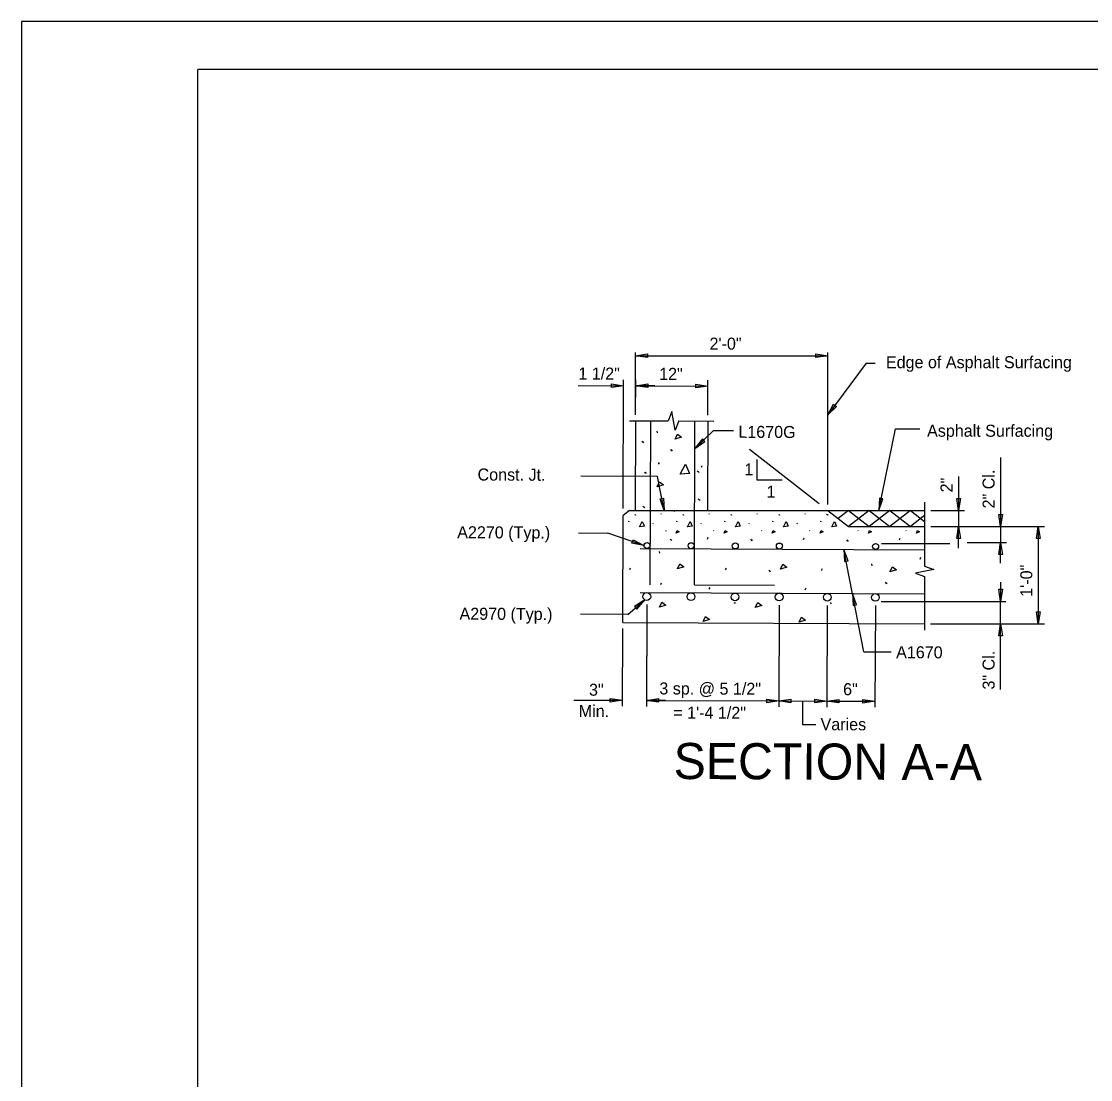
# Model space of a CAD drawing. Extents: x 2799.7 to 2896, y 515.2 to 573.9.
# Drawn here: x 2799.69 to 2829.32, y 544.56 to 573.89 of the extents above; entities that cross this region are included whole.
import ezdxf

# ---------------------------------------------------------------- set-up
doc = ezdxf.new("R2010")
doc.units = 0
for name, color, linetype in [('BR_AUTO DIMENSION', 7, 'Continuous'), ('BR_BORDER LINES', 7, 'Continuous'), ('BR_CONCRETE', 7, 'Continuous'), ('BR_DETAILS', 7, 'Continuous'), ('BR_REBAR', 7, 'Continuous'), ('BR_TABLE LINES', 7, 'Continuous'), ('BR_TEXT', 7, 'Continuous'), ('Level 31', 7, 'Continuous')]:
    doc.layers.add(name, color=color, linetype=linetype)

msp = doc.modelspace()

# ---------------------------------------------------------------- linework, layer by layer
at = {"layer": 'BR_AUTO DIMENSION'}
for p, q in [((2816.709, 562.987), (2816.709, 564.707)), ((2822.042, 560.501), (2822.042, 564.707)), ((2816.709, 564.623), (2822.042, 564.623)), ((2823.098, 564.417), (2822.042, 562.98)), ((2823.098, 564.417), (2823.349, 564.417)), ((2815.124, 563.797), (2816.38, 563.792)), ((2816.366, 560.383), (2816.38, 563.958)), ((2816.71, 562.987), (2816.714, 563.957)), ((2816.71, 562.987), (2816.714, 563.957)), ((2817.246, 563.788), (2816.713, 563.79)), ((2816.713, 563.79), (2818.713, 563.782)), ((2818.71, 562.979), (2818.714, 563.949)), ((2818.872, 562.548), (2818.354, 562.053)), ((2818.872, 562.548), (2819.425, 562.546)), ((2823.449, 560.334), (2823.908, 562.594)), ((2823.908, 562.594), (2824.59, 562.594)), ((2819.864, 562.029), (2821.798, 560.525)), ((2820.074, 561.744), (2820.074, 561.182)), ((2826.826, 561.801), (2826.826, 559.89)), ((2817.315, 561.277), (2815.196, 561.286)), ((2817.502, 560.334), (2817.315, 561.277)), ((2820.074, 561.182), (2820.772, 561.182)), ((2825.659, 561.271), (2825.659, 560.334)), ((2824.887, 560.334), (2825.826, 560.334)), ((2825.659, 560.334), (2825.659, 559.89)), ((2815.126, 559.709), (2815.941, 559.706)), ((2816.937, 559.364), (2815.941, 559.706)), ((2824.887, 559.89), (2825.826, 559.89)), ((2824.887, 559.89), (2828.037, 559.89)), ((2824.887, 559.89), (2826.992, 559.89)), ((2825.659, 559.288), (2825.659, 559.89)), ((2826.826, 559.89), (2826.826, 559.445)), ((2827.87, 559.89), (2827.87, 557.19)), ((2823.525, 559.418), (2825.421, 559.418)), ((2825.895, 559.445), (2826.992, 559.445)), ((2826.062, 559.445), (2826.992, 559.445)), ((2826.826, 558.869), (2826.826, 559.445)), ((2826.826, 558.912), (2826.826, 559.445)), ((2823.036, 556.418), (2822.484, 559.253)), ((2826.826, 558.348), (2826.826, 557.814)), ((2816.499, 557.45), (2816.968, 557.854)), ((2817.022, 557.722), (2817.01, 554.902)), ((2817.021, 557.674), (2817.01, 554.902)), ((2820.688, 557.707), (2820.677, 554.887)), ((2820.688, 557.707), (2820.677, 554.887)), ((2822.021, 557.701), (2822.01, 554.882)), ((2822.021, 557.701), (2822.01, 554.882)), ((2823.355, 557.696), (2823.343, 554.876)), ((2823.519, 557.814), (2826.968, 557.814)), ((2826.826, 557.19), (2826.826, 557.814)), ((2816.499, 557.45), (2815.188, 557.456)), ((2816.352, 557.058), (2816.343, 554.905)), ((2824.886, 557.19), (2828.037, 557.19)), ((2826.826, 555.369), (2826.826, 557.19)), ((2826.826, 556.656), (2826.826, 557.19)), ((2823.036, 556.418), (2823.788, 556.415)), ((2815.002, 555.077), (2816.344, 555.072)), ((2817.011, 555.069), (2820.677, 555.054)), ((2817.544, 555.067), (2817.011, 555.069)), ((2820.677, 555.054), (2822.011, 555.048)), ((2821.34, 555.051), (2821.34, 554.396)), ((2822.011, 555.048), (2823.344, 555.043)), ((2821.34, 554.396), (2821.706, 554.396))]:
    msp.add_line(p, q, dxfattribs=at)
for points in [[(2817.042, 564.573), (2816.709, 564.623), (2817.042, 564.673)], [(2821.709, 564.673), (2822.042, 564.623), (2821.709, 564.573)], [(2816.047, 563.843), (2816.38, 563.792), (2816.046, 563.743)], [(2817.046, 563.739), (2816.713, 563.79), (2817.047, 563.839)], [(2817.046, 563.739), (2816.713, 563.79), (2817.047, 563.839)], [(2818.38, 563.833), (2818.713, 563.782), (2818.379, 563.733)], [(2822.28, 563.219), (2822.042, 562.98), (2822.199, 563.278)], [(2818.561, 562.32), (2818.354, 562.053), (2818.63, 562.247)], [(2817.486, 560.671), (2817.502, 560.334), (2817.388, 560.651)], [(2823.466, 560.671), (2823.449, 560.334), (2823.564, 560.651)], [(2825.709, 560.668), (2825.659, 560.334), (2825.609, 560.668)], [(2826.876, 560.223), (2826.826, 559.89), (2826.776, 560.223)], [(2825.609, 559.557), (2825.659, 559.89), (2825.709, 559.557)], [(2825.609, 559.557), (2825.659, 559.89), (2825.709, 559.557)], [(2827.82, 559.557), (2827.87, 559.89), (2827.92, 559.557)], [(2816.643, 559.518), (2816.942, 559.363), (2816.61, 559.423)], [(2826.776, 559.112), (2826.826, 559.445), (2826.876, 559.112)], [(2826.776, 559.112), (2826.826, 559.445), (2826.876, 559.112)], [(2822.597, 558.935), (2822.484, 559.253), (2822.499, 558.916)], [(2822.835, 557.714), (2822.722, 558.032), (2822.736, 557.695)], [(2826.876, 558.148), (2826.826, 557.814), (2826.776, 558.148)], [(2816.748, 557.599), (2816.968, 557.854), (2816.683, 557.675)], [(2827.92, 557.523), (2827.87, 557.19), (2827.82, 557.523)], [(2826.776, 556.856), (2826.826, 557.19), (2826.876, 556.856)], [(2816.011, 555.123), (2816.344, 555.072), (2816.01, 555.023)], [(2817.344, 555.017), (2817.011, 555.069), (2817.344, 555.117)], [(2817.344, 555.017), (2817.011, 555.069), (2817.344, 555.117)], [(2820.344, 555.105), (2820.677, 555.054), (2820.344, 555.005)], [(2821.01, 555.002), (2820.677, 555.054), (2821.011, 555.102)], [(2821.677, 555.1), (2822.011, 555.048), (2821.677, 555)], [(2822.344, 554.997), (2822.011, 555.048), (2822.344, 555.097)], [(2823.011, 555.094), (2823.344, 555.043), (2823.01, 554.994)]]:
    msp.add_lwpolyline(points, close=True, dxfattribs=at)
at = {"layer": 'BR_BORDER LINES'}
for p in [(2894.359, 572.556), (2804.582, 516.556)]:
    msp.add_line(p, (2804.582, 572.556), dxfattribs=at)
at = {"layer": 'BR_CONCRETE'}
for p, q in [((2816.709, 562.82), (2816.699, 560.334)), ((2818.709, 562.812), (2818.699, 560.334)), ((2816.542, 560.334), (2816.365, 560.196)), ((2816.542, 560.334), (2822.042, 560.334)), ((2822.042, 560.334), (2822.614, 559.89)), ((2816.353, 557.225), (2816.365, 560.196)), ((2822.614, 559.89), (2824.72, 559.89)), ((2816.353, 557.225), (2824.72, 557.19))]:
    msp.add_line(p, q, dxfattribs=at)
at = {"layer": 'BR_DETAILS'}
for p, q in [((2816.542, 562.821), (2817.617, 562.816)), ((2817.906, 562.815), (2818.876, 562.811)), ((2817.301, 562.531), (2817.307, 562.481)), ((2816.883, 562.256), (2816.905, 562.223)), ((2816.906, 562.243), (2816.928, 562.21)), ((2817.678, 562.025), (2817.7, 561.992)), ((2817.7, 562.013), (2817.722, 561.979)), ((2817.349, 561.615), (2817.371, 561.665)), ((2818.42, 561.435), (2818.442, 561.402)), ((2818.442, 561.422), (2818.464, 561.389)), ((2818.537, 561.529), (2818.56, 561.579)), ((2816.956, 561.403), (2816.978, 561.37)), ((2816.978, 561.39), (2817, 561.357)), ((2818.449, 560.658), (2818.471, 560.625)), ((2818.471, 560.645), (2818.493, 560.612)), ((2824.72, 560.567), (2824.72, 558.789)), ((2816.688, 560.228), (2816.699, 560.211)), ((2816.914, 560.456), (2816.936, 560.422)), ((2816.936, 560.443), (2816.958, 560.41)), ((2817.42, 560.228), (2817.431, 560.253)), ((2817.787, 560.304), (2817.81, 560.354)), ((2818.017, 560.228), (2818.028, 560.211)), ((2818.75, 560.228), (2818.761, 560.253)), ((2819.346, 560.228), (2819.357, 560.211)), ((2820.079, 560.228), (2820.09, 560.253)), ((2820.676, 560.228), (2820.687, 560.211)), ((2821.408, 560.228), (2821.419, 560.253)), ((2822.005, 560.228), (2822.016, 560.211)), ((2822.015, 560.228), (2822.026, 560.211)), ((2816.524, 560.022), (2816.535, 560.047)), ((2816.699, 560.221), (2816.71, 560.205)), ((2817.196, 559.958), (2817.207, 559.983)), ((2817.853, 560.022), (2817.864, 560.047)), ((2818.028, 560.221), (2818.039, 560.205)), ((2818.525, 559.958), (2818.536, 559.983)), ((2819.183, 560.022), (2819.194, 560.047)), ((2819.357, 560.221), (2819.369, 560.205)), ((2819.854, 559.958), (2819.865, 559.983)), ((2820.512, 560.022), (2820.523, 560.047)), ((2820.687, 560.221), (2820.698, 560.205)), ((2821.183, 559.958), (2821.195, 559.983)), ((2821.841, 560.022), (2821.852, 560.047)), ((2822.026, 560.221), (2822.037, 560.205)), ((2817.542, 559.78), (2817.554, 559.764)), ((2818.872, 559.78), (2818.883, 559.764)), ((2820.201, 559.78), (2820.212, 559.764)), ((2821.53, 559.78), (2821.541, 559.764)), ((2822.87, 559.78), (2822.881, 559.764)), ((2824.199, 559.78), (2824.21, 559.764)), ((2817.668, 559.543), (2817.69, 559.51)), ((2817.69, 559.53), (2817.712, 559.497)), ((2818.702, 559.539), (2818.725, 559.589)), ((2819.896, 559.534), (2819.918, 559.501)), ((2819.918, 559.521), (2819.94, 559.488)), ((2821.361, 559.528), (2821.383, 559.578)), ((2822.554, 559.523), (2822.576, 559.49)), ((2822.576, 559.51), (2822.598, 559.477)), ((2824.019, 559.517), (2824.042, 559.567)), ((2817.363, 559.196), (2817.369, 559.146)), ((2823.252, 558.85), (2823.257, 558.8)), ((2824.592, 558.984), (2824.614, 559.034)), ((2816.547, 558.695), (2816.569, 558.745)), ((2819.205, 558.684), (2819.228, 558.734)), ((2820.399, 558.679), (2820.421, 558.646)), ((2820.421, 558.667), (2820.443, 558.633)), ((2821.864, 558.673), (2821.886, 558.723)), ((2824.72, 558.5), (2824.72, 557.017)), ((2817.411, 558.28), (2817.433, 558.33)), ((2818.754, 558.147), (2818.776, 558.197)), ((2821.412, 558.136), (2821.435, 558.186)), ((2823.629, 558.344), (2823.651, 558.31)), ((2823.651, 558.331), (2823.673, 558.298)), ((2819.446, 557.789), (2819.468, 557.755)), ((2822.104, 557.778), (2822.126, 557.745))]:
    msp.add_line(p, q, dxfattribs=at)
for points in [[(2817.906, 562.815), (2817.809, 562.558), (2817.714, 563.073), (2817.617, 562.816)], [(2817.807, 562.313), (2817.874, 562.452), (2817.985, 562.368), (2817.807, 562.313)], [(2817.942, 561.335), (2818.093, 561.618), (2818.208, 561.357), (2817.947, 561.335)], [(2817.307, 560.988), (2817.374, 561.127), (2817.485, 561.043), (2817.307, 560.988)], [(2816.821, 559.883), (2816.896, 560.025), (2816.954, 559.894), (2816.824, 559.883)], [(2818.15, 559.883), (2818.225, 560.025), (2818.283, 559.894), (2818.153, 559.883)], [(2819.48, 559.883), (2819.554, 560.025), (2819.613, 559.894), (2819.482, 559.883)], [(2820.809, 559.883), (2820.884, 560.025), (2820.942, 559.894), (2820.812, 559.883)], [(2822.148, 559.883), (2822.223, 560.025), (2822.282, 559.894), (2822.151, 559.883)], [(2817.834, 559.708), (2817.867, 559.778), (2817.923, 559.736), (2817.834, 559.708)], [(2819.163, 559.708), (2819.196, 559.778), (2819.252, 559.736), (2819.163, 559.708)], [(2820.492, 559.708), (2820.526, 559.778), (2820.581, 559.736), (2820.492, 559.708)], [(2821.822, 559.708), (2821.855, 559.778), (2821.911, 559.736), (2821.822, 559.708)], [(2823.161, 559.708), (2823.195, 559.778), (2823.25, 559.736), (2823.161, 559.708)], [(2824.491, 559.708), (2824.524, 559.778), (2824.579, 559.736), (2824.491, 559.708)], [(2817.868, 558.716), (2817.935, 558.854), (2818.046, 558.77), (2817.868, 558.716)], [(2820.727, 558.708), (2820.794, 558.846), (2820.905, 558.763), (2820.727, 558.708)], [(2823.758, 558.632), (2823.825, 558.77), (2823.936, 558.687), (2823.758, 558.632)], [(2824.72, 558.789), (2824.977, 558.693), (2824.463, 558.596), (2824.72, 558.5)], [(2817.369, 557.653), (2817.437, 557.792), (2817.547, 557.708), (2817.369, 557.653)], [(2820.028, 557.642), (2820.095, 557.781), (2820.206, 557.697), (2820.028, 557.642)], [(2818.584, 557.251), (2818.652, 557.39), (2818.762, 557.306), (2818.584, 557.251)], [(2821.243, 557.24), (2821.31, 557.379), (2821.421, 557.295), (2821.243, 557.24)]]:
    msp.add_lwpolyline(points, dxfattribs=at)
at = {"layer": 'BR_REBAR'}
for p, q in [((2817.116, 558.276), (2817.135, 562.818)), ((2818.339, 558.271), (2818.357, 562.813)), ((2816.839, 559.276), (2824.72, 559.244)), ((2818.339, 558.271), (2820.561, 558.262)), ((2816.834, 558.056), (2824.72, 558.024))]:
    msp.add_line(p, q, dxfattribs=at)
for centre, radius in [((2817.028, 559.361), 0.0833), ((2818.25, 559.356), 0.0833), ((2819.473, 559.351), 0.0833), ((2820.695, 559.346), 0.0833), ((2823.362, 559.335), 0.0833), ((2817.022, 557.948), 0.107), ((2818.245, 557.943), 0.107), ((2819.467, 557.938), 0.107), ((2820.689, 557.933), 0.107), ((2822.022, 557.927), 0.107), ((2823.356, 557.922), 0.107)]:
    msp.add_circle(centre, radius, dxfattribs=at)
at = {"layer": 'BR_TABLE LINES'}
for p, q in [((2822.047, 560.334), (2824.72, 560.334)), ((2822.614, 560.334), (2822.328, 560.112)), ((2822.614, 560.334), (2823.185, 559.89)), ((2823.185, 560.334), (2822.614, 559.89)), ((2823.757, 560.334), (2823.185, 559.89)), ((2823.185, 560.334), (2823.757, 559.89)), ((2823.757, 560.334), (2824.328, 559.89)), ((2824.328, 560.334), (2823.757, 559.89)), ((2824.328, 560.334), (2824.72, 560.03)), ((2824.72, 560.195), (2824.328, 559.89))]:
    msp.add_line(p, q, dxfattribs=at)
at = {"layer": 'Level 31'}
msp.add_line((2895.694, 573.89), (2799.693, 573.89), dxfattribs=at)
msp.add_lwpolyline([(2799.693, 573.89), (2799.693, 515.223), (2895.694, 515.223), (2895.694, 573.89)], dxfattribs=at)

# ---------------------------------------------------------------- texts
at = {"layer": 'BR_AUTO DIMENSION'}
for s, height, rotation, p in [('2\'-0"', 0.3333, 0, (2818.76, 564.79)), ('1 1/2"', 0.3333, 359.7654, (2815.125, 563.963)), ('12"', 0.3333, 359.7654, (2817.363, 563.954)), ('2" Cl.', 0.3333, 90, (2826.659, 560.39)), ('2"', 0.3333, 90, (2825.493, 560.834)), ('1\'-0"', 0.3333, 90, (2827.704, 557.941)), ('3" Cl.', 0.3333, 90, (2826.659, 555.369)), ('3"', 0.3333, 359.7654, (2815.42, 555.198)), ('3 sp. @ 5 1/2"', 0.33333, 359.7654, (2817.369, 555.234)), ('6"', 0.3333, 359.7654, (2822.46, 555.213)), ('Min.', 0.3333, 359.7654, (2815.135, 554.608)), (' = 1\'-4 1/2"', 0.3333, 359.7654, (2817.63, 554.566)), ('Varies', 0.3333, 359.7654, (2821.835, 554.243))]:
    msp.add_text(s, height=height, rotation=rotation, dxfattribs=at).set_placement(p)
at = {"layer": 'BR_TEXT'}
for s, height, rotation, p in [('Edge of Asphalt Surfacing', 0.3333, 0, (2823.647, 564.276)), ('L1670G', 0.3333, 359.7654, (2819.559, 562.347)), ('Asphalt Surfacing', 0.3333, 0, (2824.787, 562.376)), ('Const. Jt.', 0.3333, 359.7654, (2812.332, 561.163)), ('1', 0.333, 0, (2819.725, 561.304)), ('1', 0.333, 0, (2820.341, 560.688)), ('A2270 (Typ.)', 0.3333, 359.7654, (2811.768, 559.564)), ('A2970 (Typ.)', 0.3333, 359.7654, (2811.832, 557.305)), ('A1670', 0.3333, 359.7654, (2823.929, 556.238)), ('SECTION A-A', 1, 359.7654, (2817.763, 552.89))]:
    msp.add_text(s, height=height, rotation=rotation, dxfattribs=at).set_placement(p)

doc.saveas('drawing.dxf')
